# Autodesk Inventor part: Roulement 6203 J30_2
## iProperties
Author: Administrateur
Created: 2004-01
Part Number: Roulement 6203 J30_2
Material: Par défaut
Document SubType Name: Modélisation
Designer: Administrateur
Control State: 0
Master: False
Checked Out: False
PropertySet Name: Design Tracking Control
Shininess: 20.0
Angle Display Precision: 2
Document Length Units: 11269
Document Angle Units: 11283
Document Time Units: 11279
Document Mass Units: 11290
Document Length Units Precision: 3
Document Angle Units Precision: 2
Compacted: False
PropertySet Name: _Private Model Information
Density: 0.0
Volumn: 0.0
Area: 0.0
PropertySet Name: Model Information
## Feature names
1. Base1
